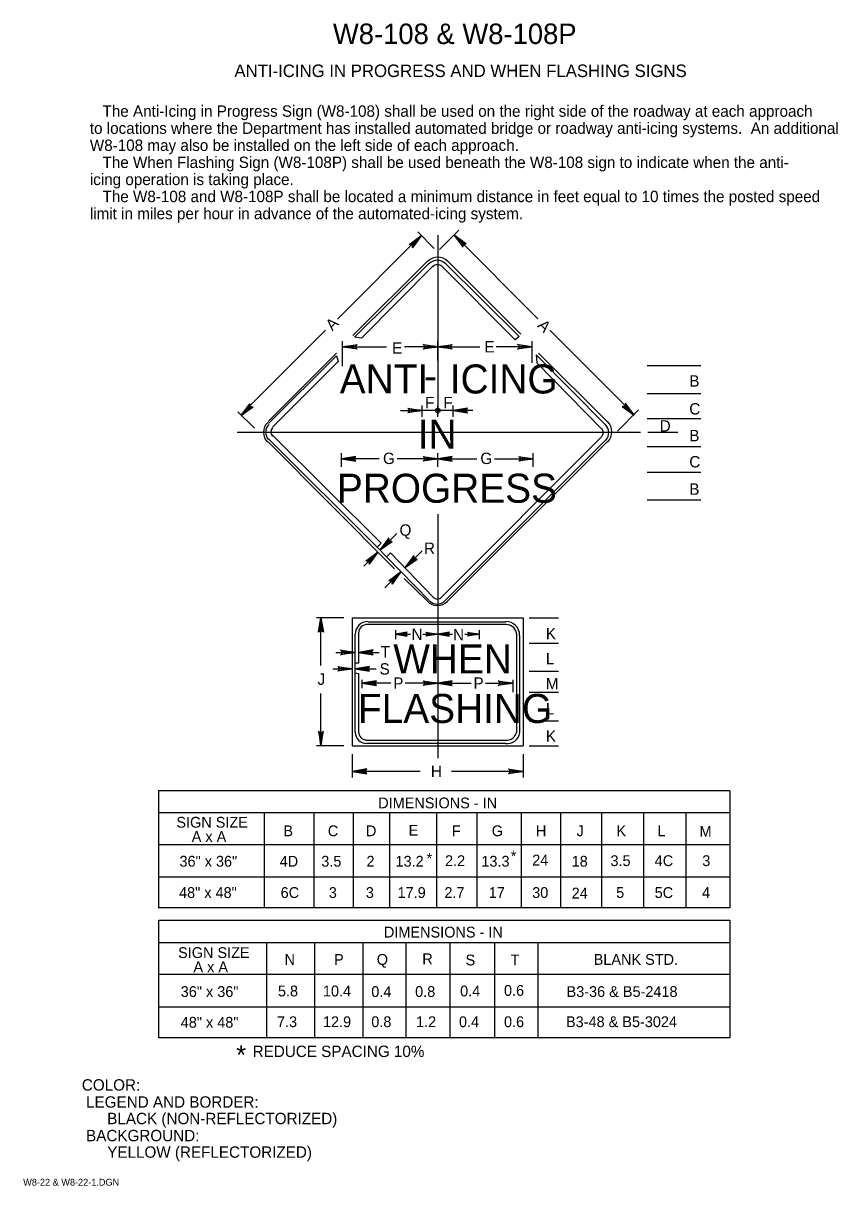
# Model space of a CAD drawing. Extents: x 0.012 to 0.191, y 0.004 to 0.259.
import ezdxf

# ---------------------------------------------------------------- set-up
doc = ezdxf.new("R2010")
doc.units = 0
for name, color, linetype in [('1', 7, 'Continuous'), ('11', 7, 'Continuous'), ('12', 7, 'Continuous'), ('2', 7, 'Continuous'), ('3', 7, 'Continuous')]:
    doc.layers.add(name, color=color, linetype=linetype)

# ---------------------------------------------------------------- blocks, each defined once
blk = doc.blocks.new('RARROW')
at = {"layer": '3'}
for p, q in [((-2.156, 0.28500000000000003), (-2.2665, 0.384625)), ((-2.2665, 0.384625), (0, 0)), ((0, 0), (-2.2665, -0.379125)), ((-2.156, 0.28500000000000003), (-2.075625, 0.12075)), ((0, 0), (-2.156, 0.28500000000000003)), ((-2.14975, -0.2705), (0, 0)), ((-2.075625, 0.12075), (0, 0)), ((0, 0), (-2.074, -0.108)), ((-2.2665, -0.379125), (-2.14975, -0.2705)), ((-2.074, -0.108), (-2.14975, -0.2705))]:
    blk.add_line(p, q, dxfattribs=at)

msp = doc.modelspace()

# ---------------------------------------------------------------- linework, layer by layer
at = {"layer": '1'}
for p, q in [((0.09440823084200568, 0.14726681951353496), (0.09073101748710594, 0.1436061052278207)), ((0.09025816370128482, 0.14313312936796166), (0.08715267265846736, 0.14004156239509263)), ((0.090125, 0.14425), (0.092125, 0.142125)), ((0.09995093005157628, 0.14343432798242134), (0.09620714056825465, 0.13970733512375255)), ((0.09533241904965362, 0.13883204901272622), (0.09176349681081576, 0.13527912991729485)), ((0.08525, 0.116625), (0.08525, 0.11875000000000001))]:
    msp.add_line(p, q, dxfattribs=at)
msp.add_circle((0.10340009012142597, 0.17424899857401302), 0.0004877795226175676, dxfattribs=at)
at = {"layer": '11'}
for p, q in [((0.08475, 0.19075), (0.10125, 0.207125)), ((0.1055, 0.207125), (0.121625, 0.191)), ((0.085125, 0.19037500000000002), (0.1015, 0.206625)), ((0.10237500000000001, 0.20600000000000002), (0.08662500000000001, 0.19012500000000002)), ((0.10225000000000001, 0.205875), (0.10237500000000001, 0.20600000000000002)), ((0.120375, 0.18975), (0.10425, 0.20600000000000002)), ((0.105, 0.206625), (0.12125, 0.1905)), ((0.08662500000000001, 0.19012500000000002), (0.085125, 0.19037500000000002)), ((0.12125, 0.1905), (0.120375, 0.18975)), ((0.066125, 0.171875), (0.081125, 0.186875)), ((0.14025, 0.171125), (0.125, 0.1865)), ((0.125, 0.1865), (0.12512500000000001, 0.18475)), ((0.1255, 0.186875), (0.140625, 0.171875)), ((0.06625, 0.171375), (0.081125, 0.18625)), ((0.0815, 0.185), (0.067125, 0.170625)), ((0.081125, 0.18625), (0.0815, 0.185)), ((0.12512500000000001, 0.18475), (0.139375, 0.17025)), ((0.067125, 0.168875), (0.091, 0.145125)), ((0.093875, 0.1395), (0.066125, 0.167375)), ((0.090125, 0.14425), (0.06625, 0.168)), ((0.139375, 0.1685), (0.10425, 0.13325)), ((0.105, 0.1325), (0.14025, 0.16775)), ((0.140625, 0.167375), (0.1055, 0.132375)), ((0.091, 0.145125), (0.090125, 0.14425)), ((0.093, 0.14300000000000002), (0.092125, 0.142125)), ((0.10237500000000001, 0.13325), (0.093, 0.14300000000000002)), ((0.092125, 0.142125), (0.1015, 0.1325)), ((0.101125, 0.132375), (0.096, 0.137375)), ((0.088125, 0.12787500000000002), (0.11837500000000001, 0.12787500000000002)), ((0.08525, 0.11875000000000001), (0.08525, 0.12512500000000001)), ((0.11850000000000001, 0.12725), (0.088, 0.12725)), ((0.12075, 0.104125), (0.12075, 0.125)), ((0.121375, 0.124875), (0.121375, 0.10350000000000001)), ((0.08775000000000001, 0.10187500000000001), (0.11862500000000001, 0.10187500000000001)), ((0.11825000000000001, 0.101125), (0.08775000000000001, 0.101125))]:
    msp.add_line(p, q, dxfattribs=at)
for points in [[(0.08600000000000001, 0.12537500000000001), (0.08600000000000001, 0.11875000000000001), (0.08525, 0.11875000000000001)], [(0.08525, 0.10362500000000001), (0.08525, 0.116625), (0.08600000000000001, 0.1165), (0.08600000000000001, 0.10362500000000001)]]:
    msp.add_lwpolyline(points, dxfattribs=at)
for centre, radius, start, end in [((0.10341658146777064, 0.2049392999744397), 0.0030032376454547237, 44.96247777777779, 135.03752500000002), ((0.10330135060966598, 0.20481699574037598), 0.0024649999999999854, 44.91796944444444, 135), ((0.10335402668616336, 0.20487489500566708), 0.0014163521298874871, 48.551211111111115, 138.60145555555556), ((0.06818795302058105, 0.16943647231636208), 0.0030600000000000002, 134.16918611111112, 224.9628638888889), ((0.06806348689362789, 0.1694728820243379), 0.0024649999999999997, 135, 223.34960833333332), ((0.13850564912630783, 0.16942422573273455), 0.002445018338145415, 315.96693055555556, 44.95301666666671), ((0.138388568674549, 0.1695488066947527), 0.0032107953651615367, 315.82084444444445, 44.80693055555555), ((0.06802184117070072, 0.16952040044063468), 0.0012749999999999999, 135, 225), ((0.13850564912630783, 0.16942422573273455), 0.0012550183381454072, 315.96693055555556, 44.95301666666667), ((0.10331250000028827, 0.13414685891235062), 0.0012974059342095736, 223.73079444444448, 316.2692083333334), ((0.10331250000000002, 0.13446767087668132), 0.00302728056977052, 223.73079166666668, 316.2692055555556), ((0.1032618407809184, 0.13413572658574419), 0.0023867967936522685, 224.2005777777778, 316.7389916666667), ((0.08806223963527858, 0.1251420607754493), 0.0027865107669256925, 89.98362500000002, 179.98362500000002), ((0.11834103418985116, 0.1248895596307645), 0.0030340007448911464, 359.7250472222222, 89.72504722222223), ((0.08790592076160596, 0.12531663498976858), 0.0019356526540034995, 87.21413333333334, 177.21413333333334), ((0.11850434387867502, 0.1250122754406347), 0.0022186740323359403, 0, 90), ((0.08775685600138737, 0.10359593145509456), 0.002481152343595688, 179.74110000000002, 269.7411), ((0.08774091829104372, 0.10360761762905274), 0.0017155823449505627, 178.22643333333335, 268.2264333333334), ((0.11863925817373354, 0.10388925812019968), 0.0027915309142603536, 261.9844111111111, 351.9844111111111), ((0.11855871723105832, 0.1040765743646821), 0.0022025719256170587, 271.72448333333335, 1.7244833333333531)]:
    msp.add_arc(centre, radius, start, end, dxfattribs=at)
at = {"layer": '3'}
for p, q in [((0.08141658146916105, 0.19431151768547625), (0.09972929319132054, 0.21274880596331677)), ((0.10262500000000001, 0.209875), (0.099, 0.2135)), ((0.10337500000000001, 0.21275), (0.10337500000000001, 0.173375)), ((0.10375000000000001, 0.209625), (0.108, 0.213875)), ((0.12537500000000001, 0.194375), (0.107, 0.212875)), ((0.07875, 0.19187500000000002), (0.06025, 0.173375)), ((0.128, 0.19187500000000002), (0.1465, 0.173375)), ((0.0825, 0.184), (0.0825, 0.1895)), ((0.10337500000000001, 0.18525), (0.10337500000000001, 0.1895)), ((0.124125, 0.18475), (0.124125, 0.1895)), ((0.0825, 0.18825), (0.092125, 0.18825)), ((0.10337500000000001, 0.18825), (0.096125, 0.18825)), ((0.10337500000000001, 0.18825), (0.112625, 0.18825)), ((0.124125, 0.18825), (0.11625, 0.18825)), ((0.149375, 0.184125), (0.161125, 0.184125)), ((0.149375, 0.178), (0.161125, 0.178)), ((0.063125, 0.170375), (0.059500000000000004, 0.17400000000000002)), ((0.09525, 0.17425000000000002), (0.1, 0.17425000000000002)), ((0.1, 0.172875), (0.1, 0.175375)), ((0.10675, 0.17425000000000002), (0.1, 0.17425000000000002)), ((0.10337500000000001, 0.172875), (0.10337500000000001, 0.175375)), ((0.10675, 0.172875), (0.10675, 0.175375)), ((0.111125, 0.17425000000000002), (0.10675, 0.17425000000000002)), ((0.142875, 0.16975), (0.1475, 0.174375)), ((0.149375, 0.17250000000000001), (0.161125, 0.17250000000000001)), ((0.059375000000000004, 0.1695), (0.147875, 0.1695)), ((0.1495, 0.1695), (0.156125, 0.1695)), ((0.149375, 0.166375), (0.161125, 0.166375)), ((0.08225, 0.161875), (0.08225, 0.164875)), ((0.0905, 0.163625), (0.08225, 0.163625)), ((0.10337500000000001, 0.163625), (0.0945, 0.163625)), ((0.10337500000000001, 0.161875), (0.10337500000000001, 0.164875)), ((0.10337500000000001, 0.163625), (0.112, 0.163625)), ((0.115875, 0.163625), (0.124375, 0.163625)), ((0.124375, 0.161875), (0.124375, 0.164875)), ((0.149375, 0.16075), (0.161125, 0.16075)), ((0.149375, 0.154625), (0.161125, 0.154625)), ((0.10337500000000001, 0.1515), (0.10337500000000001, 0.13)), ((0.08275, 0.12875), (0.07675, 0.12875)), ((0.07775, 0.11825000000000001), (0.07775, 0.12875)), ((0.084625, 0.12875), (0.084625, 0.100625)), ((0.084625, 0.12875), (0.122125, 0.12875)), ((0.10337500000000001, 0.13), (0.10337500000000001, 0.097875)), ((0.122125, 0.12875), (0.122125, 0.100625)), ((0.1235, 0.12875), (0.129875, 0.12875)), ((0.094125, 0.126), (0.094125, 0.124)), ((0.094125, 0.12512500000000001), (0.097375, 0.12512500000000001)), ((0.100125, 0.12512500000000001), (0.10337500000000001, 0.12512500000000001)), ((0.10337500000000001, 0.12512500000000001), (0.106625, 0.12512500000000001)), ((0.109375, 0.12512500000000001), (0.1125, 0.12512500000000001)), ((0.1125, 0.126), (0.1125, 0.124)), ((0.1235, 0.123125), (0.129875, 0.123125)), ((0.081, 0.121125), (0.08525, 0.121125)), ((0.08600000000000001, 0.121125), (0.0905, 0.121125)), ((0.080375, 0.11750000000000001), (0.084625, 0.11750000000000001)), ((0.08525, 0.11750000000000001), (0.089875, 0.11750000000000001)), ((0.08675000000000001, 0.115125), (0.08675000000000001, 0.11325)), ((0.11987500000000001, 0.115125), (0.11987500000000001, 0.112375)), ((0.1235, 0.117), (0.129875, 0.117)), ((0.093125, 0.114375), (0.08675000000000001, 0.114375)), ((0.10337500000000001, 0.114375), (0.09625, 0.114375)), ((0.10337500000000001, 0.114375), (0.11075, 0.114375)), ((0.113875, 0.114375), (0.11987500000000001, 0.114375)), ((0.1235, 0.112375), (0.129875, 0.112375)), ((0.07775, 0.100625), (0.07775, 0.112125)), ((0.1235, 0.106125), (0.129875, 0.106125)), ((0.08275, 0.100625), (0.07675, 0.100625)), ((0.084625, 0.100625), (0.122125, 0.100625)), ((0.1235, 0.100625), (0.129875, 0.100625)), ((0.084625, 0.09875), (0.084625, 0.093625)), ((0.122125, 0.09875), (0.122125, 0.093625)), ((0.0995, 0.095), (0.084625, 0.095)), ((0.122125, 0.095), (0.106375, 0.095)), ((0.1675, 0.09075), (0.042, 0.09075)), ((0.0420538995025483, 0.09075340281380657), (0.0420538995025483, 0.06500340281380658)), ((0.16750747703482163, 0.09075340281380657), (0.16750747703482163, 0.06499713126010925)), ((0.16750747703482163, 0.08587840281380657), (0.0420538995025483, 0.08587840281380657)), ((0.0653038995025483, 0.08587840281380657), (0.0653038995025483, 0.06500340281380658)), ((0.0761597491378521, 0.08587840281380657), (0.0761597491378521, 0.06500340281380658)), ((0.08485048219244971, 0.08587840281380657), (0.08485048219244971, 0.06500340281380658)), ((0.09279507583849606, 0.08587840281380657), (0.09279507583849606, 0.06500340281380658)), ((0.10312377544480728, 0.08587840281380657), (0.10312377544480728, 0.06500340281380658)), ((0.11197470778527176, 0.08587840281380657), (0.11197470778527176, 0.06500340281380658)), ((0.12167861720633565, 0.08587840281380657), (0.12167861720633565, 0.06500340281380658)), ((0.13035576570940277, 0.08587840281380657), (0.13035576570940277, 0.06500340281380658)), ((0.13934176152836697, 0.08587840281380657), (0.13934176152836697, 0.06499713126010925)), ((0.14857814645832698, 0.08587840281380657), (0.14857814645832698, 0.06499713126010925)), ((0.15786147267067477, 0.08587840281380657), (0.15786147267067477, 0.06499713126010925)), ((0.16750747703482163, 0.07887840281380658), (0.0420538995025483, 0.07887840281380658)), ((0.16750747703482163, 0.07175340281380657), (0.0420538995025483, 0.07175340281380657)), ((0.1675, 0.065), (0.042, 0.065)), ((0.04210524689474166, 0.06227871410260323), (0.04210524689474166, 0.036497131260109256)), ((0.16750747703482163, 0.06224713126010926), (0.042166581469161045, 0.06224713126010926)), ((0.16750747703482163, 0.06227871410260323), (0.16750747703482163, 0.036497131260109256)), ((0.16750747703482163, 0.05736272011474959), (0.04210524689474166, 0.05736272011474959)), ((0.06582451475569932, 0.05740371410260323), (0.06582451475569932, 0.036528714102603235)), ((0.07630761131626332, 0.05740371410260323), (0.07630761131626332, 0.036528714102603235)), ((0.08692630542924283, 0.05740371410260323), (0.08692630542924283, 0.036528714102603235)), ((0.096366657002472, 0.05740371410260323), (0.096366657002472, 0.036528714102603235)), ((0.10604923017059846, 0.05740371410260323), (0.10604923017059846, 0.036528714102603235)), ((0.11586017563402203, 0.05740371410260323), (0.11586017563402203, 0.036528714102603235)), ((0.12539155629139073, 0.05736272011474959), (0.12539155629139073, 0.036528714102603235)), ((0.16750747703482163, 0.05036272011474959), (0.04210524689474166, 0.05036272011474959)), ((0.16750747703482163, 0.04323772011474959), (0.04210524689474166, 0.04323772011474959)), ((0.16750747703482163, 0.036497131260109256), (0.042166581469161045, 0.036497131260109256))]:
    msp.add_line(p, q, dxfattribs=at)

# ---------------------------------------------------------------- block references
for p, xscale, yscale, rotation in [((0.09975, 0.212625), 0.0014063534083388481, 0.0013911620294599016, 45), ((0.107, 0.21275), 0.0014063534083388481, -0.0013911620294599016, 135), ((0.0825, 0.18825), 0.0014063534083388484, 0.001391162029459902, 180), ((0.10337500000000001, 0.18825), 0.0014063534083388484, 0.001391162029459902, 180), ((0.06025, 0.173125), 0.0014063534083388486, 0.0013911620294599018, -135), ((0.10675, 0.17425000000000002), 0.0014063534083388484, -0.001391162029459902, 180), ((0.1465, 0.17325000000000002), 0.0014063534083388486, -0.0013911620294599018, -45), ((0.08225, 0.163625), 0.0014063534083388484, -0.001391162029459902, 180), ((0.10337500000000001, 0.163625), 0.0014063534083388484, -0.001391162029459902, 180), ((0.09075, 0.143625), 0.0014063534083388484, -0.0013911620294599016, -135), ((0.09025, 0.143125), 0.0014063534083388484, 0.0013911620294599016, 44.99999999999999), ((0.09625, 0.13975), 0.0014063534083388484, -0.0013911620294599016, -135), ((0.09525, 0.13875), 0.0014063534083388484, 0.0013911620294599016, 44.99999999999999), ((0.07775, 0.12875), 0.0014063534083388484, 0.001391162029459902, 90), ((0.094125, 0.12512500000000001), 0.0011391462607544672, -0.0011268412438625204, 180), ((0.10337500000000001, 0.12512500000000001), 0.0011391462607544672, -0.0011268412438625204, 180), ((0.08600000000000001, 0.121125), 0.0014063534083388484, -0.001391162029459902, 180), ((0.08525, 0.11750000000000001), 0.0014063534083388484, -0.001391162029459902, 180), ((0.08675000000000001, 0.114375), 0.0014063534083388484, -0.001391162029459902, 180), ((0.10337500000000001, 0.114375), 0.0014063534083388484, -0.001391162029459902, 180), ((0.07775, 0.100625), 0.0014063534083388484, -0.001391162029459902, -90.00000000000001), ((0.084625, 0.095), 0.0014063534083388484, -0.001391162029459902, 180)]:
    msp.add_blockref('RARROW', p, dxfattribs=dict(at, xscale=xscale, yscale=yscale, rotation=rotation))
for p, xscale, yscale in [((0.10337500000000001, 0.18825), 0.0014063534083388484, 0.001391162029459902), ((0.124125, 0.18825), 0.0014063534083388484, 0.001391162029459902), ((0.1, 0.17425000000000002), 0.0014063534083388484, 0.001391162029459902), ((0.10337500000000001, 0.163625), 0.0014063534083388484, 0.001391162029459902), ((0.124375, 0.163625), 0.0014063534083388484, 0.001391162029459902), ((0.10337500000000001, 0.12512500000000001), 0.0011391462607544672, 0.0011268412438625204), ((0.1125, 0.12512500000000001), 0.0011391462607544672, 0.0011268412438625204), ((0.08525, 0.121125), 0.0014063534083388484, 0.001391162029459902), ((0.084625, 0.11750000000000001), 0.0014063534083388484, 0.001391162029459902), ((0.10337500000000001, 0.114375), 0.0014063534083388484, 0.001391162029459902), ((0.11987500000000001, 0.114375), 0.0014063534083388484, 0.001391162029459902), ((0.122125, 0.095), 0.0014063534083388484, 0.001391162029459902)]:
    msp.add_blockref('RARROW', p, dxfattribs=dict(at, xscale=xscale, yscale=yscale))

# ---------------------------------------------------------------- texts
at = {"layer": '1'}
for s, height, p in [('W8-108 & W8-108P', 0.0045000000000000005, (0.08036863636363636, 0.25475000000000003)), ('ANTI-ICING IN PROGRESS AND WHEN FLASHING SIGNS', 0.00275025, (0.058750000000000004, 0.2475)), ('COLOR:', 0.0024997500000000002, (0.02525, 0.024875)), (' LEGEND AND BORDER:', 0.0024997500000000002, (0.02525, 0.021125)), ('      BLACK (NON-REFLECTORIZED)', 0.0024997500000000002, (0.02525, 0.0175)), (' BACKGROUND:', 0.0024997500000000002, (0.02525, 0.01375)), ('      YELLOW (REFLECTORIZED)', 0.0024997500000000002, (0.02525, 0.010125)), ('W8-22 & W8-22-1.DGN', 0.0015, (0.012375, 0.004))]:
    msp.add_text(s, height=height, dxfattribs=at).set_placement(p)
at = {"layer": '12'}
for s, p in [('ANTI  ICING', (0.081875, 0.178)), ('IN', (0.099, 0.165875)), ('PROGRESS', (0.08125, 0.154)), ('WHEN', (0.093625, 0.1165)), ('FLASHING', (0.085875, 0.105625))]:
    msp.add_text(s, height=0.0063750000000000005, dxfattribs=at).set_placement(p)
at = {"layer": '2'}
for s, p in [('   The Anti-Icing in Progress Sign (W8-108) shall be used on the right side of the roadway at each approach', (0.027, 0.23877094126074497)), ('to locations where the Department has installed automated bridge or roadway anti-icing systems.  An additional ', (0.027, 0.23502119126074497)), ('W8-108 may also be installed on the left side of each approach.', (0.027, 0.23127144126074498)), ('   The When Flashing Sign (W8-108P) shall be used beneath the W8-108 sign to indicate when the anti-', (0.027, 0.22752169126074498)), ('icing operation is taking place.', (0.027, 0.22377194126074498)), ('   The W8-108 and W8-108P shall be located a minimum distance in feet equal to 10 times the posted speed ', (0.027, 0.22002219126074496)), ('limit in miles per hour in advance of the automated-icing system.', (0.027, 0.216272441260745))]:
    msp.add_text(s, height=0.0024997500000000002, dxfattribs=at).set_placement(p)
at = {"layer": '3'}
for rotation, p in [(45, (0.08025, 0.19162500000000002)), (315, (0.12512500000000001, 0.19275))]:
    msp.add_text('A', height=0.0024997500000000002, rotation=rotation, dxfattribs=at).set_placement(p)
for s, height, p in [('E', 0.0024997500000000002, (0.093375, 0.18675)), ('E', 0.0024997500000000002, (0.113625, 0.187)), ('-', 0.0063750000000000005, (0.100375, 0.17875)), ('B', 0.0024997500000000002, (0.15862500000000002, 0.1795)), ('F', 0.0024997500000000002, (0.100625, 0.17475000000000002)), ('F', 0.0024997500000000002, (0.104625, 0.17475000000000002)), ('C', 0.0024997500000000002, (0.15862500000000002, 0.173375)), ('D', 0.0024997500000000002, (0.152125, 0.169625)), ('B', 0.0024997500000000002, (0.15862500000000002, 0.1675)), ('G', 0.0024997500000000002, (0.091375, 0.1625)), ('G', 0.0024997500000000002, (0.11275, 0.1625)), ('C', 0.0024997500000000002, (0.15862500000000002, 0.16175)), ('B', 0.0024997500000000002, (0.15862500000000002, 0.15575)), ('Q', 0.0024997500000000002, (0.095, 0.14675)), ('R', 0.0024997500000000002, (0.100375, 0.14275000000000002)), ('N', 0.0024997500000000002, (0.097625, 0.123875)), ('N', 0.0024997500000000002, (0.10675, 0.12375)), ('K', 0.0024997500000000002, (0.12712500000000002, 0.124)), ('T', 0.0024997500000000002, (0.090875, 0.12)), ('L', 0.0024997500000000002, (0.12712500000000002, 0.11850000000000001)), ('S', 0.0024997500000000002, (0.090625, 0.11625)), ('J', 0.0024997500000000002, (0.077, 0.114)), ('P', 0.0024997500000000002, (0.093625, 0.113125)), ('P', 0.0024997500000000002, (0.11125, 0.113125)), ('M', 0.0024997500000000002, (0.12712500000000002, 0.113)), ('L', 0.0024997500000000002, (0.12712500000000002, 0.1075)), ('K', 0.0024997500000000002, (0.12712500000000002, 0.1015)), ('H', 0.0024997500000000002, (0.10187500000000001, 0.09375)), ('DIMENSIONS - IN', 0.0023752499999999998, (0.09031659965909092, 0.08687500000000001)), ('SIGN SIZE', 0.0023752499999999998, (0.046, 0.082625)), ('A x A', 0.0023752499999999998, (0.049375, 0.0795)), ('B', 0.0023752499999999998, (0.0695, 0.08075)), ('C', 0.0023752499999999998, (0.07925, 0.08075)), ('D', 0.0023752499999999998, (0.08762500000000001, 0.08075)), ('E', 0.0023752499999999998, (0.097, 0.080875)), ('F', 0.0023752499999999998, (0.1065, 0.08075)), ('G', 0.0023752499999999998, (0.11525, 0.08075)), ('H', 0.0023752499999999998, (0.12494556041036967, 0.08075)), ('J', 0.0023752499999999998, (0.133875, 0.08075)), ('K', 0.0023752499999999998, (0.142625, 0.08075)), ('L', 0.0023752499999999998, (0.151625, 0.08075)), ('M', 0.0023752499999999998, (0.160875, 0.080625)), ('*', 0.0023752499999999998, (0.10093154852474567, 0.07469077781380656)), ('*', 0.0023752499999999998, (0.11943154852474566, 0.07519077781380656)), ('24', 0.0023752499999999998, (0.12412363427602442, 0.07431577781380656)), ('36" x 36"', 0.0023752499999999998, (0.04668738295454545, 0.07406577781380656)), ('4D', 0.0023752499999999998, (0.06869354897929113, 0.07406577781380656)), ('3.5', 0.0023752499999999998, (0.07781746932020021, 0.07406577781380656)), ('2', 0.0023752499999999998, (0.08774105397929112, 0.07406577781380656)), ('13.2', 0.0023752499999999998, (0.09411605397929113, 0.07406577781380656)), ('2.2', 0.0023752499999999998, (0.10499105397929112, 0.07419077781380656)), ('13.3', 0.0023752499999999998, (0.11297413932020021, 0.07406577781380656)), ('18', 0.0023752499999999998, (0.1328016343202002, 0.07406577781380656)), ('3.5', 0.0023752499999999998, (0.1413142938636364, 0.07419077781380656)), ('4C', 0.0023752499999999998, (0.15102140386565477, 0.07419077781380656)), ('3', 0.0023752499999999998, (0.16147413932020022, 0.07419077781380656)), ('48" x 48"', 0.0023752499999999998, (0.04658978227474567, 0.06719077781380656)), ('6C', 0.0023752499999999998, (0.06889640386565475, 0.06719077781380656)), ('3', 0.0023752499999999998, (0.07947413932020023, 0.06719077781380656)), ('3', 0.0023752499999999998, (0.08759913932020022, 0.06719077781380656)), ('17.9', 0.0023752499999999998, (0.09456818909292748, 0.06719077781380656)), ('2.7', 0.0023752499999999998, (0.10485021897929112, 0.06719077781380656)), ('17', 0.0023752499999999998, (0.11460021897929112, 0.06719077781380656)), ('30', 0.0023752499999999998, (0.12413011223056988, 0.06719077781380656)), ('24', 0.0023752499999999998, (0.13280307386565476, 0.06706577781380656)), ('5', 0.0023752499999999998, (0.14256746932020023, 0.06719077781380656)), ('5C', 0.0023752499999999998, (0.15102140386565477, 0.06719077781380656)), ('4', 0.0023752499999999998, (0.16142807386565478, 0.06719077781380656)), ('DIMENSIONS - IN', 0.0023752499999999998, (0.09156659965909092, 0.0585)), ('SIGN SIZE', 0.0023752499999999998, (0.046375, 0.054)), ('N', 0.0023752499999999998, (0.06975, 0.0525)), ('P', 0.0023752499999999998, (0.080625, 0.0525)), ('Q', 0.0023752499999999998, (0.09, 0.0525)), ('R', 0.0023752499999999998, (0.1, 0.052625)), ('S', 0.0023752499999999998, (0.1095, 0.052375)), ('T', 0.0023752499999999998, (0.11937500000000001, 0.052375)), ('BLANK STD.', 0.0023752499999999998, (0.137625, 0.0525)), ('A x A', 0.0023752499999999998, (0.04975, 0.050875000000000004)), ('36" x 36"', 0.0023752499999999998, (0.04696478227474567, 0.045440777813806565)), ('5.8', 0.0023752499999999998, (0.06830163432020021, 0.045565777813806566)), ('10.4', 0.0023752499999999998, (0.07817807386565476, 0.045565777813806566)), ('0.4', 0.0023752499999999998, (0.08880307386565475, 0.045440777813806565)), ('0.8', 0.0023752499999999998, (0.09842663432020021, 0.045440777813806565)), ('0.4', 0.0023752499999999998, (0.10830307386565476, 0.045565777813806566)), ('0.6', 0.0023752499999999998, (0.11793959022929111, 0.045690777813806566)), ('B3-36 & B5-2418', 0.0023752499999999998, (0.13167663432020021, 0.045440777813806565)), ('48" x 48"', 0.0023752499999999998, (0.04696478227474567, 0.038690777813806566)), ('7.3', 0.0023752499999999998, (0.06809913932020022, 0.038815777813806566)), ('12.9', 0.0023752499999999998, (0.07819318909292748, 0.038815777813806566)), ('0.8', 0.0023752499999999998, (0.0888016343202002, 0.038815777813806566)), ('1.2', 0.0023752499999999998, (0.09861605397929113, 0.038815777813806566)), ('0.4', 0.0023752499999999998, (0.10805307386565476, 0.038815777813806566)), ('0.6', 0.0023752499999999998, (0.11793959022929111, 0.038815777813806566)), ('B3-48 & B5-3024', 0.0023752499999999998, (0.13155307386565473, 0.038815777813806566)), ('*', 0.004205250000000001, (0.059125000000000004, 0.030625)), ('REDUCE SPACING 10%', 0.0024997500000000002, (0.06275, 0.03225))]:
    msp.add_text(s, height=height, dxfattribs=at).set_placement(p)

doc.saveas('drawing.dxf')
